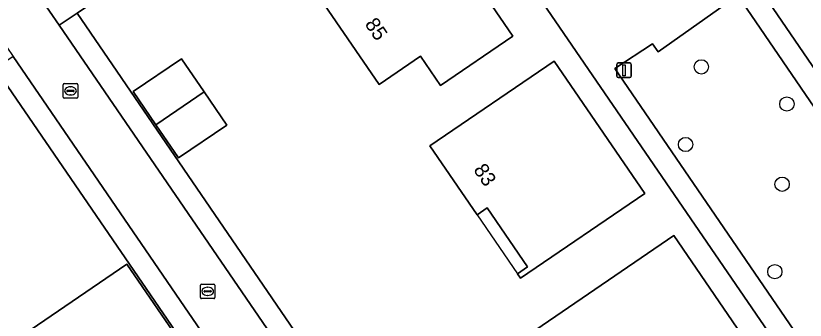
# Model space of a CAD drawing. Extents: x 155275 to 156265, y 382654 to 383635.
# Drawn here: x 155630.7 to 155684.7, y 383396.1 to 383417 of the extents above; entities that cross this region are included whole.
import ezdxf

# ---------------------------------------------------------------- set-up
doc = ezdxf.new("R2010")
doc.units = 0
for name, color, linetype in [('IMGEO_Boom', 7, 'Continuous'), ('IMGEO_Erf', 7, 'Continuous'), ('IMGEO_Groenvoorziening', 7, 'Continuous'), ('IMGEO_Kolk', 7, 'Continuous'), ('IMGEO_Lichtmast', 7, 'Continuous'), ('IMGEO_Pand', 7, 'Continuous'), ('IMGEO_Pand_nummerreeks', 7, 'Continuous'), ('IMGEO_Pand_overbouw', 7, 'Continuous'), ('IMGEO_Rijbaan_lokaal_open', 7, 'Continuous'), ('IMGEO_Voetpad_open', 7, 'Continuous')]:
    doc.layers.add(name, color=color, linetype=linetype)

msp = doc.modelspace()

# ---------------------------------------------------------------- linework, layer by layer
at = {"layer": 'IMGEO_Boom'}
for centre in [(155677.633, 383413.507), (155683.485, 383410.961), (155676.553, 383408.188), (155683.161, 383405.464), (155682.661, 383399.471)]:
    msp.add_circle(centre, 0.489, dxfattribs=at)
at = {"layer": 'IMGEO_Erf'}
for points in [[(155689.573, 383454.56), (155686.888, 383452.74), (155667.515, 383439.536), (155668.209, 383438.49), (155691.786, 383403.993), (155718.509, 383364.995), (155740.511, 383380.044), (155700.458, 383438.718), (155700.636, 383438.742)], [(155657.299, 383431.777), (155657.022, 383432.185), (155634.905, 383417.186), (155657.35, 383384.321), (155685.798, 383342.799), (155707.917, 383357.778), (155706.87, 383359.32)], [(155655.578, 383412.294), (155651.839, 383417.758), (155649.396, 383421.329), (155646.571, 383419.417), (155643.961, 383423.23), (155649.985, 383427.353), (155651.544, 383425.076), (155657.196, 383428.869), (155660.665, 383423.782), (155660.852, 383423.507), (155659.82, 383422.803), (155664.727, 383415.607), (155659.785, 383412.236), (155658.413, 383414.231)], [(155641.843, 383407.266), (155640.292, 383409.54), (155638.74, 383411.813), (155642.04, 383414.064), (155643.596, 383411.794), (155645.151, 383409.523)], [(155659.053, 383408.1), (155667.557, 383413.907), (155673.759, 383404.826), (155665.255, 383399.019), (155665.047, 383399.324), (155665.736, 383399.795), (155662.968, 383403.848), (155662.279, 383403.377)], [(155626.344, 383411.364), (155605.932, 383397.438), (155603.987, 383396.057), (155605.754, 383393.471), (155605.827, 383393.52), (155653.992, 383322.86), (155654.882, 383321.57), (155677.497, 383337.038), (155680.25, 383338.906), (155654.839, 383376.063), (155629.299, 383413.395)], [(155664.262, 383386.851), (155660.887, 383391.796), (155675.749, 383401.941), (155680.373, 383395.166), (155673.358, 383390.385), (155672.109, 383392.206)], [(155625.365, 383382.665), (155621.893, 383387.683), (155628.009, 383391.842), (155627.505, 383392.602), (155638.312, 383399.989), (155642.265, 383394.224)]]:
    msp.add_lwpolyline(points, close=True, dxfattribs=at)
at = {"layer": 'IMGEO_Groenvoorziening'}
msp.add_lwpolyline([(155671.715, 383413.396), (155689.641, 383387.16), (155697.682, 383392.701), (155680.127, 383418.418), (155674.678, 383414.539), (155674.299, 383415.086)], close=True, dxfattribs=at)
at = {"layer": 'IMGEO_Kolk'}
for p, q in [((155633.951, 383411.434), (155633.951, 383412.286)), ((155634.026, 383412.36), (155634.878, 383412.36)), ((155634.253, 383411.903), (155634.651, 383411.903)), ((155634.439, 383412.14), (155634.464, 383412.14)), ((155634.952, 383412.286), (155634.952, 383411.434)), ((155634.878, 383411.36), (155634.026, 383411.36)), ((155634.21, 383411.854), (155634.21, 383411.866)), ((155634.648, 383411.817), (155634.25, 383411.817)), ((155634.462, 383411.58), (155634.437, 383411.58)), ((155634.694, 383411.866), (155634.694, 383411.854)), ((155643.342, 383397.697), (155643.342, 383398.549)), ((155643.417, 383398.623), (155644.269, 383398.623)), ((155643.83, 383398.403), (155643.855, 383398.403)), ((155644.343, 383398.549), (155644.343, 383397.697)), ((155643.601, 383398.117), (155643.601, 383398.129)), ((155644.039, 383398.08), (155643.641, 383398.08)), ((155643.644, 383398.166), (155644.042, 383398.166)), ((155643.853, 383397.843), (155643.828, 383397.843)), ((155644.085, 383398.129), (155644.085, 383398.117)), ((155644.269, 383397.623), (155643.417, 383397.623))]:
    msp.add_line(p, q, dxfattribs=at)
for points in [[(155633.951, 383411.434), (155633.951, 383412.286)], [(155634.026, 383412.36), (155634.878, 383412.36)], [(155634.952, 383412.286), (155634.952, 383411.434)], [(155634.878, 383411.36), (155634.026, 383411.36)], [(155643.342, 383397.697), (155643.342, 383398.549)], [(155643.417, 383398.623), (155644.269, 383398.623)], [(155644.343, 383398.549), (155644.343, 383397.697)], [(155644.269, 383397.623), (155643.417, 383397.623)]]:
    msp.add_lwpolyline(points, dxfattribs=at)
for centre, radius, start, end in [((155634.028, 383412.284), 0.0765, 91.552, 178.448), ((155634.028, 383412.284), 0.0765, 91.552, 178.448), ((155634.25, 383411.863), 0.0403, 85.8775, 175.7526), ((155634.655, 383411.865), 0.0386, 1.7309, 96.639), ((155634.876, 383412.284), 0.0765, 1.552, 88.448), ((155634.876, 383412.284), 0.0765, 1.552, 88.448), ((155634.028, 383411.436), 0.0765, 181.552, 268.448), ((155634.028, 383411.436), 0.0765, 181.552, 268.448), ((155634.247, 383411.853), 0.0366, 178.938, 274.7102), ((155634.651, 383411.86), 0.043, 264.8664, 352.4533), ((155634.876, 383411.436), 0.0765, 271.552, 358.448), ((155634.876, 383411.436), 0.0765, 271.552, 358.448), ((155643.419, 383398.547), 0.0765, 91.552, 178.448), ((155643.419, 383398.547), 0.0765, 91.552, 178.448), ((155644.267, 383398.547), 0.0765, 1.552, 88.448), ((155644.267, 383398.547), 0.0765, 1.552, 88.448), ((155643.641, 383398.126), 0.0403, 85.8775, 175.7526), ((155643.638, 383398.116), 0.0366, 178.938, 274.7102), ((155644.042, 383398.123), 0.043, 264.8664, 352.4533), ((155644.046, 383398.128), 0.0386, 1.7309, 96.639), ((155643.419, 383397.699), 0.0765, 181.552, 268.448), ((155643.419, 383397.699), 0.0765, 181.552, 268.448), ((155644.267, 383397.699), 0.0765, 271.552, 358.448), ((155644.267, 383397.699), 0.0765, 271.552, 358.448)]:
    msp.add_arc(centre, radius, start, end, dxfattribs=at)
for centre, major_axis, ratio, start_param, end_param in [((155634.438, 383411.86), (-0.387, 0.002), 0.722429, 4.712389, 7.853982), ((155634.463, 383411.86), (-0.39, 0.002), 0.717154, 1.570796, 4.712389), ((155643.829, 383398.123), (-0.387, 0.002), 0.722429, 4.712389, 7.853982), ((155643.854, 383398.123), (-0.39, 0.002), 0.717154, 1.570796, 4.712389)]:
    msp.add_ellipse(centre, major_axis=major_axis, ratio=ratio, start_param=start_param, end_param=end_param, dxfattribs=at)
at = {"layer": 'IMGEO_Lichtmast'}
for p, q in [((155671.846, 383412.877), (155671.846, 383413.677)), ((155671.846, 383413.677), (155671.846, 383412.877)), ((155671.946, 383413.777), (155672.736, 383413.777)), ((155672.736, 383413.777), (155671.946, 383413.777)), ((155672.836, 383413.677), (155672.836, 383412.877)), ((155672.836, 383412.877), (155672.836, 383413.677)), ((155672.736, 383412.777), (155671.946, 383412.777)), ((155671.946, 383412.777), (155672.736, 383412.777))]:
    msp.add_line(p, q, dxfattribs=at)
msp.add_lwpolyline([(155672.266, 383413.652), (155672.416, 383413.652), (155672.416, 383412.902), (155672.266, 383412.902), (155672.266, 383413.652)], dxfattribs=at)
for centre, start, end in [((155671.946, 383413.677), 90, 180), ((155671.946, 383413.677), 90, 180), ((155672.736, 383413.677), 0, 90), ((155672.736, 383413.677), 360, 90), ((155671.946, 383412.877), 180, 270), ((155671.946, 383412.877), 180, 270), ((155672.736, 383412.877), 270, 0), ((155672.736, 383412.877), 270, 0)]:
    msp.add_arc(centre, 0.1, start, end, dxfattribs=at)
at = {"layer": 'IMGEO_Pand'}
for points in [[(155660.665, 383423.782), (155651.839, 383417.758), (155655.578, 383412.294), (155658.413, 383414.231), (155659.785, 383412.236), (155664.727, 383415.607), (155659.82, 383422.803), (155660.852, 383423.507)], [(155642.04, 383414.064), (155638.74, 383411.813), (155640.292, 383409.54), (155643.596, 383411.794)], [(155659.053, 383408.1), (155662.279, 383403.377), (155662.968, 383403.848), (155665.736, 383399.795), (155665.047, 383399.324), (155665.255, 383399.019), (155673.759, 383404.826), (155667.557, 383413.907)], [(155643.596, 383411.794), (155640.292, 383409.54), (155641.843, 383407.266), (155645.151, 383409.523)], [(155675.749, 383401.941), (155660.887, 383391.796), (155664.262, 383386.851), (155672.109, 383392.206), (155673.358, 383390.385), (155680.373, 383395.166)], [(155625.365, 383382.665), (155642.265, 383394.224), (155638.312, 383399.989), (155627.505, 383392.602), (155628.009, 383391.842), (155621.893, 383387.683)]]:
    msp.add_lwpolyline(points, close=True, dxfattribs=at)
at = {"layer": 'IMGEO_Pand_overbouw'}
msp.add_lwpolyline([(155662.279, 383403.377), (155665.047, 383399.324), (155665.736, 383399.795), (155662.968, 383403.848)], close=True, dxfattribs=at)
at = {"layer": 'IMGEO_Rijbaan_lokaal_open'}
for points in [[(155633.677, 383416.365), (155632.353, 383418.3)], [(155685.887, 383340.048), (155684.569, 383341.975), (155633.677, 383416.365)], [(155629.214, 383416.139), (155630.534, 383414.209), (155681.461, 383339.737), (155682.726, 383337.887)]]:
    msp.add_lwpolyline(points, dxfattribs=at)
at = {"layer": 'IMGEO_Voetpad_open'}
for points in [[(155691.786, 383403.993), (155668.209, 383438.49), (155667.515, 383439.536), (155666.824, 383440.579), (155664.403, 383444.228), (155663.948, 383444.914), (155662.707, 383444.065), (155665.605, 383439.742), (155666.371, 383438.6), (155666.772, 383438.002), (155677.272, 383422.615), (155674.699, 383420.892), (155674.334, 383421.454), (155668.829, 383417.591), (155659.219, 383431.603), (155658.27, 383432.997), (155657.468, 383434.175), (155654.542, 383438.474), (155653.319, 383437.636), (155653.784, 383436.951), (155656.244, 383433.33), (155657.022, 383432.185), (155657.299, 383431.777), (155706.87, 383359.32)], [(155632.353, 383418.3), (155633.677, 383416.365), (155634.905, 383417.186), (155657.022, 383432.185)]]:
    msp.add_lwpolyline(points, dxfattribs=at)
for points in [[(155689.641, 383387.16), (155671.715, 383413.396), (155674.299, 383415.086), (155674.678, 383414.539), (155680.127, 383418.418), (155697.682, 383392.701)], [(155634.905, 383417.186), (155633.677, 383416.365), (155684.569, 383341.975), (155685.798, 383342.799), (155657.35, 383384.321)], [(155630.534, 383414.209), (155629.299, 383413.395), (155654.839, 383376.063), (155680.25, 383338.906), (155681.461, 383339.737)]]:
    msp.add_lwpolyline(points, close=True, dxfattribs=at)

# ---------------------------------------------------------------- texts
at = {"layer": 'IMGEO_Pand_nummerreeks'}
for s, rotation, p in [('85', 304.3816, (155654.559, 383416.439)), ('83', 304.1366, (155661.999, 383406.452))]:
    msp.add_text(s, height=1, rotation=rotation, dxfattribs=at).set_placement(p)

doc.saveas('drawing.dxf')
